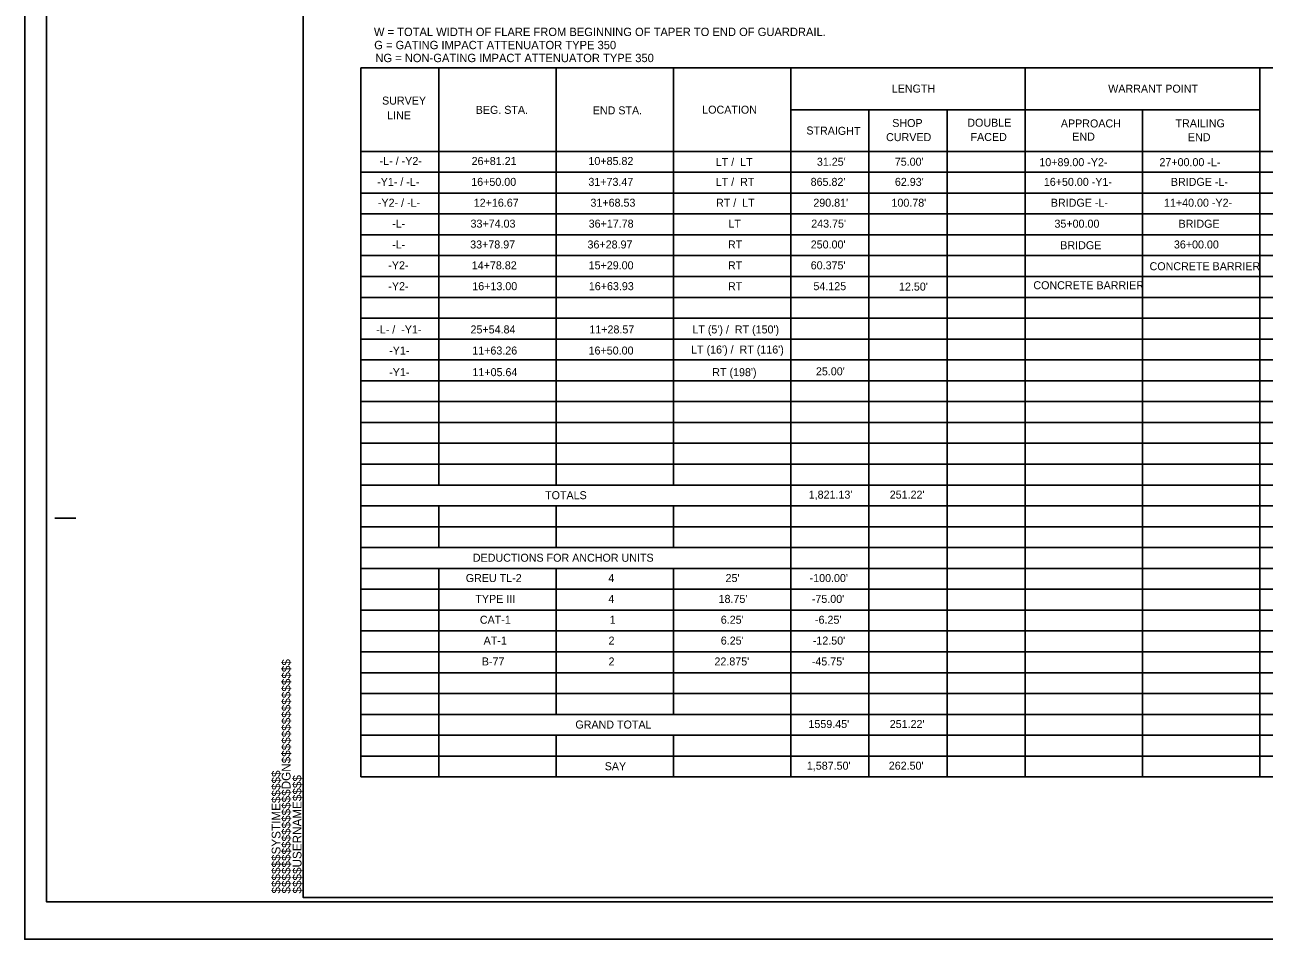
# Model space of a CAD drawing. Extents: x 1318055 to 1318380, y 620349 to 620480.
# Drawn here: x 1318124.1 to 1318198.4, y 620370.4 to 620425.3 of the extents above; entities that cross this region are included whole.
import ezdxf

# ---------------------------------------------------------------- set-up
doc = ezdxf.new("R2010")
doc.units = 0
for name, color, linetype in [('Sheet Cutting Line CELL', 7, 'Continuous'), ('Sheet Plot Border Inside CELL', 7, 'Continuous'), ('Sheet Plot Border Outside CELL', 7, 'Continuous'), ('Sheet Summary Combination CELL', 7, 'Continuous'), ('Sheet Summary Combination Grid CELL', 7, 'Continuous')]:
    doc.layers.add(name, color=color, linetype=linetype)

msp = doc.modelspace()

# ---------------------------------------------------------------- linework, layer by layer
at = {"layer": 'Sheet Cutting Line CELL'}
for p, q in [((1318124.055, 620480.437), (1318124.055, 620370.437)), ((1318124.055, 620370.437), (1318292.455, 620370.437))]:
    msp.add_line(p, q, dxfattribs=at)
at = {"layer": 'Sheet Plot Border Inside CELL'}
msp.add_lwpolyline([(1318292.005, 620478.192), (1318125.355, 620478.192), (1318125.355, 620372.682), (1318292.005, 620372.682)], close=True, dxfattribs=at)
at = {"layer": 'Sheet Plot Border Outside CELL'}
msp.add_lwpolyline([(1318292.455, 620480.437), (1318124.055, 620480.437), (1318124.055, 620370.437), (1318292.455, 620370.437)], close=True, dxfattribs=at)
at = {"layer": 'Sheet Summary Combination CELL'}
for p, q in [((1318125.865, 620395.687), (1318127.115, 620395.687)), ((1318140.755, 620385.236), (1318140.755, 620385.236))]:
    msp.add_line(p, q, dxfattribs=at)
msp.add_lwpolyline([(1318290.755, 620477.937), (1318140.755, 620477.937), (1318140.755, 620372.937), (1318290.755, 620372.937)], close=True, dxfattribs=at)
at = {"layer": 'Sheet Summary Combination Grid CELL'}
for p, q in [((1318144.204, 620422.666), (1318283.854, 620422.666)), ((1318144.204, 620422.666), (1318144.204, 620380.166)), ((1318148.889, 620422.666), (1318148.889, 620397.666)), ((1318155.924, 620422.666), (1318155.924, 620397.666)), ((1318162.954, 620422.666), (1318162.954, 620397.666)), ((1318169.984, 620422.666), (1318169.984, 620380.166)), ((1318184.049, 620422.666), (1318184.049, 620380.166)), ((1318198.109, 620422.666), (1318198.109, 620380.166)), ((1318169.984, 620420.166), (1318198.109, 620420.166)), ((1318174.674, 620420.166), (1318174.674, 620380.166)), ((1318179.359, 620420.166), (1318179.359, 620380.166)), ((1318191.079, 620420.166), (1318191.079, 620380.166)), ((1318144.204, 620417.666), (1318283.854, 620417.666)), ((1318144.204, 620416.416), (1318283.854, 620416.416)), ((1318144.204, 620415.166), (1318283.854, 620415.166)), ((1318144.204, 620413.916), (1318283.854, 620413.916)), ((1318144.204, 620412.666), (1318283.854, 620412.666)), ((1318144.204, 620411.416), (1318283.854, 620411.416)), ((1318144.204, 620410.166), (1318283.854, 620410.166)), ((1318144.204, 620408.916), (1318283.854, 620408.916)), ((1318144.204, 620407.666), (1318283.854, 620407.666)), ((1318144.204, 620406.416), (1318283.854, 620406.416)), ((1318144.204, 620405.166), (1318283.854, 620405.166)), ((1318144.204, 620403.916), (1318283.854, 620403.916)), ((1318144.204, 620402.666), (1318283.854, 620402.666)), ((1318144.204, 620401.416), (1318283.854, 620401.416)), ((1318144.204, 620400.166), (1318283.854, 620400.166)), ((1318144.204, 620398.916), (1318283.854, 620398.916)), ((1318144.204, 620397.666), (1318283.854, 620397.666)), ((1318144.204, 620396.416), (1318283.854, 620396.416)), ((1318148.889, 620396.416), (1318148.889, 620393.916)), ((1318155.924, 620396.416), (1318155.924, 620393.916)), ((1318162.954, 620396.416), (1318162.954, 620393.916)), ((1318144.204, 620395.166), (1318283.854, 620395.166)), ((1318144.204, 620393.916), (1318283.854, 620393.916)), ((1318144.204, 620392.666), (1318283.854, 620392.666)), ((1318148.889, 620392.666), (1318148.889, 620382.666)), ((1318155.924, 620392.666), (1318155.924, 620383.916)), ((1318162.954, 620392.666), (1318162.954, 620383.916)), ((1318144.204, 620391.416), (1318283.854, 620391.416)), ((1318144.204, 620390.166), (1318283.854, 620390.166)), ((1318144.204, 620388.916), (1318283.854, 620388.916)), ((1318144.204, 620387.666), (1318283.854, 620387.666)), ((1318144.204, 620386.416), (1318283.854, 620386.416)), ((1318144.204, 620385.166), (1318283.854, 620385.166)), ((1318144.204, 620385.166), (1318283.854, 620385.166)), ((1318144.204, 620383.916), (1318283.854, 620383.916)), ((1318144.204, 620382.666), (1318283.854, 620382.666)), ((1318148.889, 620382.666), (1318148.889, 620380.166)), ((1318155.924, 620382.666), (1318155.924, 620380.166)), ((1318162.954, 620382.666), (1318162.954, 620380.166)), ((1318144.204, 620381.416), (1318283.854, 620381.416)), ((1318144.204, 620380.166), (1318283.854, 620380.166))]:
    msp.add_line(p, q, dxfattribs=at)

# ---------------------------------------------------------------- texts
at = {"layer": 'Sheet Summary Combination CELL'}
for s, height, p in [('W = TOTAL WIDTH OF FLARE FROM BEGINNING OF TAPER TO END OF GUARDRAIL.', 0.50001, (1318144.992, 620424.581)), ('G = GATING IMPACT ATTENUATOR TYPE 350', 0.50001, (1318145.009, 620423.792)), ('NG = NON-GATING IMPACT ATTENUATOR TYPE 350', 0.50001, (1318145.079, 620423.017)), ('LENGTH', 0.48, (1318176.044, 620421.191)), ('WARRANT POINT', 0.48, (1318189.024, 620421.186)), ('SURVEY', 0.48, (1318145.479, 620420.471)), ('LINE', 0.48, (1318145.784, 620419.586)), ('BEG. STA.', 0.48, (1318151.094, 620419.916)), ('END STA.', 0.48, (1318158.114, 620419.886)), ('LOCATION', 0.48, (1318164.679, 620419.926)), ('SHOP', 0.48, (1318176.074, 620419.126)), ('DOUBLE', 0.48, (1318180.574, 620419.146)), ('APPROACH', 0.48, (1318186.184, 620419.101)), ('TRAILING', 0.48, (1318193.059, 620419.111)), ('CURVED', 0.48, (1318175.704, 620418.281)), ('FACED', 0.48, (1318180.769, 620418.291)), ('END', 0.48, (1318186.869, 620418.311)), ('END', 0.48, (1318193.804, 620418.276)), ('-L- / -Y2-', 0.48, (1318145.336, 620416.849)), ('26+81.21', 0.48, (1318150.849, 620416.849)), ('10+85.82', 0.48, (1318157.854, 620416.849)), ('LT /  LT', 0.48, (1318165.489, 620416.792)), ("31.25'", 0.48, (1318171.554, 620416.806)), ("75.00'", 0.48, (1318176.226, 620416.806)), ('10+89.00 -Y2-', 0.48, (1318184.895, 620416.78)), ('27+00.00 -L-', 0.48, (1318192.096, 620416.78)), ('-Y1- / -L-', 0.48, (1318145.183, 620415.599)), ('16+50.00', 0.48, (1318150.828, 620415.599)), ('31+73.47', 0.48, (1318157.852, 620415.599)), ('LT /  RT', 0.48, (1318165.489, 620415.599)), ("865.82'", 0.48, (1318171.18, 620415.599)), ("62.93'", 0.48, (1318176.232, 620415.599)), ('16+50.00 -Y1-', 0.48, (1318185.163, 620415.599)), ('BRIDGE -L-', 0.48, (1318192.779, 620415.599)), ('-Y2- / -L-', 0.48, (1318145.229, 620414.349)), ('12+16.67', 0.48, (1318150.977, 620414.349)), ('31+68.53', 0.48, (1318157.976, 620414.349)), ('RT /  LT', 0.48, (1318165.507, 620414.349)), ("290.81'", 0.48, (1318171.341, 620414.349)), ("100.78'", 0.48, (1318176.026, 620414.349)), ('BRIDGE -L-', 0.48, (1318185.583, 620414.349)), ('11+40.00 -Y2-', 0.48, (1318192.368, 620414.349)), ('-L-', 0.48, (1318146.082, 620413.096)), ('33+74.03', 0.48, (1318150.785, 620413.096)), ('36+17.78', 0.48, (1318157.868, 620413.096)), ('LT', 0.48, (1318166.251, 620413.096)), ("243.75'", 0.48, (1318171.215, 620413.096)), ('35+00.00', 0.48, (1318185.801, 620413.093)), ('BRIDGE', 0.48, (1318193.243, 620413.087)), ('-L-', 0.48, (1318146.082, 620411.846)), ('33+78.97', 0.48, (1318150.764, 620411.846)), ('36+28.97', 0.48, (1318157.799, 620411.846)), ('RT', 0.48, (1318166.222, 620411.846)), ("250.00'", 0.48, (1318171.185, 620411.846)), ('36+00.00', 0.48, (1318192.963, 620411.846)), ('BRIDGE', 0.48, (1318186.15, 620411.801)), ('-Y2-', 0.48, (1318145.854, 620410.596)), ('14+78.82', 0.48, (1318150.859, 620410.596)), ('15+29.00', 0.48, (1318157.867, 620410.596)), ('RT', 0.48, (1318166.222, 620410.596)), ("60.375'", 0.48, (1318171.185, 620410.596)), ('CONCRETE BARRIER', 0.48, (1318191.504, 620410.541)), ('-Y2-', 0.48, (1318145.854, 620409.346)), ('16+13.00', 0.48, (1318150.89, 620409.346)), ('16+63.93', 0.48, (1318157.878, 620409.346)), ('RT', 0.48, (1318166.222, 620409.346)), ('54.125', 0.48, (1318171.347, 620409.346)), ("12.50'", 0.48, (1318176.477, 620409.321)), ('CONCRETE BARRIER', 0.48, (1318184.538, 620409.402)), ('-L- /  -Y1-', 0.48, (1318145.131, 620406.753)), ('25+54.84', 0.48, (1318150.784, 620406.753)), ('11+28.57', 0.48, (1318157.91, 620406.753)), ("LT (5') /  RT (150')", 0.48, (1318164.086, 620406.753)), ('-Y1-', 0.48, (1318145.907, 620405.487)), ('11+63.26', 0.48, (1318150.888, 620405.487)), ('16+50.00', 0.48, (1318157.864, 620405.487)), ("LT (16') /  RT (116')", 0.48, (1318164.011, 620405.547)), ('-Y1-', 0.48, (1318145.907, 620404.191)), ('11+05.64', 0.48, (1318150.899, 620404.191)), ("RT (198')", 0.48, (1318165.281, 620404.191)), ("25.00'", 0.48, (1318171.496, 620404.241)), ('TOTALS', 0.48, (1318155.255, 620396.816)), ("1,821.13'", 0.48, (1318171.063, 620396.849)), ("251.22'", 0.48, (1318175.923, 620396.849)), ('DEDUCTIONS FOR ANCHOR UNITS', 0.48, (1318150.924, 620393.066)), ('GREU TL-2', 0.48, (1318150.498, 620391.849)), ('4', 0.48, (1318159.048, 620391.849)), ("25'", 0.48, (1318166.077, 620391.849)), ("-100.00'", 0.48, (1318171.118, 620391.849)), ('TYPE III', 0.48, (1318151.073, 620390.599)), ('4', 0.48, (1318159.048, 620390.599)), ("18.75'", 0.48, (1318165.659, 620390.599)), ("-75.00'", 0.48, (1318171.251, 620390.599)), ('CAT-1', 0.48, (1318151.344, 620389.349)), ('1', 0.48, (1318159.13, 620389.349)), ("6.25'", 0.48, (1318165.792, 620389.349)), ("-6.25'", 0.48, (1318171.441, 620389.349)), ('AT-1', 0.48, (1318151.57, 620388.099)), ('2', 0.48, (1318159.061, 620388.099)), ("6.25'", 0.48, (1318165.792, 620388.099)), ("-12.50'", 0.48, (1318171.308, 620388.099)), ('B-77', 0.48, (1318151.461, 620386.849)), ('2', 0.48, (1318159.061, 620386.849)), ("22.875'", 0.48, (1318165.412, 620386.849)), ("-45.75'", 0.48, (1318171.251, 620386.849)), ('GRAND TOTAL', 0.48, (1318157.073, 620383.066)), ("1559.45'", 0.48, (1318171.048, 620383.099)), ("251.22'", 0.48, (1318175.923, 620383.099)), ("1,587.50'", 0.48, (1318170.953, 620380.599)), ("262.50'", 0.48, (1318175.865, 620380.599)), ('SAY', 0.48, (1318158.83, 620380.566))]:
    msp.add_text(s, height=height, dxfattribs=at).set_placement(p)
for s, height, rotation, p in [('STRAIGHT', 0.48, 359.36414, (1318170.919, 620418.681)), ('$$$$$$$$$$$$$$$$DGN$$$$$$$$$$$$$$$$', 0.525, 90, (1318139.99, 620373.174)), ('$$$$$$SYSTIME$$$$$', 0.525, 90, (1318139.385, 620373.174)), ('$$$$USERNAME$$$$', 0.525, 90, (1318140.647, 620373.175))]:
    msp.add_text(s, height=height, rotation=rotation, dxfattribs=at).set_placement(p)

doc.saveas('drawing.dxf')
